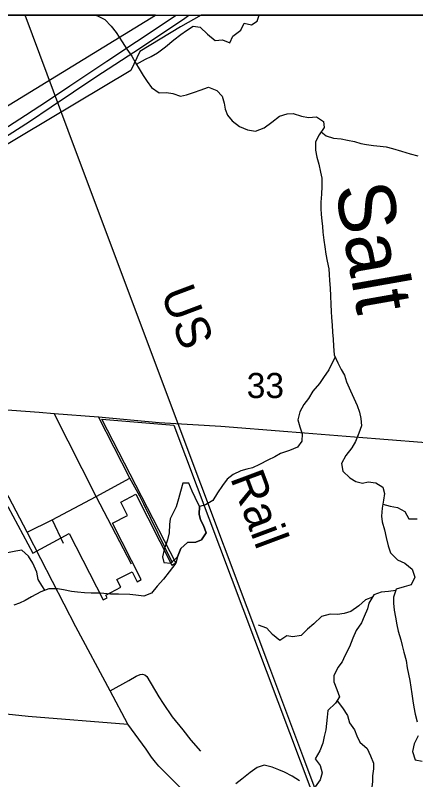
# Model space of a CAD drawing. Extents: x 0 to 34, y 0 to 22.
# Drawn here: x 7.308 to 7.976, y 19.626 to 20.9 of the extents above; entities that cross this region are included whole.
import ezdxf

# ---------------------------------------------------------------- set-up
doc = ezdxf.new("R2010")
doc.units = 0
for name, color, linetype in [('GM_X_City_Street', 7, 'Continuous'), ('GM_X_Corporation', 7, 'Continuous'), ('GM_X_Major_River', 7, 'Continuous'), ('GM_X_Major_River_Text', 7, 'Continuous'), ('GM_X_Minor_Lake', 7, 'Continuous'), ('GM_X_Minor_River', 7, 'Continuous'), ('GM_X_Rail_Line', 7, 'Continuous'), ('GM_X_Rail_Line_Text', 7, 'Continuous'), ('GM_X_Section_Text', 7, 'Continuous'), ('GM_X_State_Route', 7, 'Continuous'), ('GM_X_Township_Road', 7, 'Continuous'), ('SH_Data', 7, 'Continuous')]:
    doc.layers.add(name, color=color, linetype=linetype)

msp = doc.modelspace()

# ---------------------------------------------------------------- linework, layer by layer
at = {"layer": 'GM_X_City_Street'}
for points in [[(7.5486, 20.221), (7.6513, 20.215), (7.7633, 20.2061), (7.8743, 20.1973), (7.9869, 20.1886), (8.0786, 20.1811), (8.1861, 20.1725), (8.2502, 20.1677), (8.257, 20.1674), (8.2667, 20.1684), (8.2777, 20.1709), (8.2899, 20.1745), (8.3049, 20.18), (8.3207, 20.1872), (8.3351, 20.1944), (8.3579, 20.209), (8.4567, 20.2898), (8.4843, 20.3102), (8.5164, 20.3311)], [(7.2032, 20.2492), (7.3486, 20.2383), (7.3732, 20.236), (7.4471, 20.2305), (7.5486, 20.221)]]:
    msp.add_lwpolyline(points, dxfattribs=at)
at = {"layer": 'GM_X_Corporation'}
for points in [[(7.2218, 20.7043), (7.5423, 20.9), (5.1364, 20.9)], [(8.0548, 20.9), (7.6183, 20.9), (7.5838, 20.8809), (7.5164, 20.8398), (7.501, 20.8077), (7.2272, 20.6445)], [(7.2961, 20.0811), (7.3375, 20.0037), (7.3985, 20.0362), (7.4549, 19.9255), (7.4616, 19.929), (7.4595, 19.9333), (7.4846, 19.9466), (7.4781, 19.9593), (7.5032, 19.9726), (7.5118, 19.9557), (7.5185, 19.9593), (7.4706, 20.0533), (7.4956, 20.0664), (7.4844, 20.0884), (7.5095, 20.1018), (7.5696, 19.9836), (7.5763, 19.9872), (7.4527, 20.2266), (7.573, 20.2166), (7.8422, 19.5022)]]:
    msp.add_lwpolyline(points, dxfattribs=at)
at = {"layer": 'GM_X_Major_River'}
for points in [[(7.4415, 20.9), (7.4456, 20.8989), (7.4577, 20.8931), (7.4686, 20.8817), (7.4765, 20.8714), (7.4869, 20.8557), (7.4948, 20.8435), (7.503, 20.8317), (7.509, 20.821), (7.515, 20.8107), (7.5217, 20.7997), (7.5284, 20.7894), (7.5356, 20.7795), (7.5484, 20.7706), (7.5609, 20.7713), (7.5711, 20.7697), (7.5843, 20.765), (7.5942, 20.7672), (7.6075, 20.7717), (7.617, 20.7754), (7.6307, 20.7802), (7.6447, 20.7748), (7.6533, 20.7653), (7.657, 20.7535), (7.6588, 20.7436), (7.6625, 20.7333), (7.67, 20.7238), (7.6824, 20.7146), (7.696, 20.7091), (7.7093, 20.7068), (7.7237, 20.7123), (7.7363, 20.7221), (7.7493, 20.7319), (7.7618, 20.7356), (7.7721, 20.7362), (7.7857, 20.732), (7.7978, 20.7296), (7.8107, 20.7306), (7.8224, 20.7229), (7.8238, 20.7127), (7.8154, 20.701), (7.8092, 20.6889), (7.8094, 20.6752), (7.8116, 20.6635), (7.8146, 20.6521), (7.8175, 20.6384), (7.8197, 20.6285), (7.8199, 20.6148), (7.8191, 20.6019), (7.8182, 20.5887), (7.8181, 20.5777), (7.8188, 20.5678), (7.8198, 20.5575), (7.8209, 20.548), (7.8216, 20.5386), (7.8233, 20.5253), (7.8248, 20.5142), (7.8266, 20.5021), (7.8287, 20.4903), (7.8313, 20.4774), (7.8323, 20.4679)], [(7.8323, 20.4679), (7.8326, 20.458), (7.834, 20.4451), (7.8343, 20.4326), (7.8349, 20.4178), (7.8356, 20.406), (7.8359, 20.3965), (7.8369, 20.3836), (7.8376, 20.3719), (7.8386, 20.3601), (7.8393, 20.3487), (7.8403, 20.3339), (7.8463, 20.3206), (7.8518, 20.3095), (7.8575, 20.3), (7.8612, 20.2893), (7.8675, 20.2741), (7.873, 20.2619), (7.8786, 20.2494), (7.8827, 20.2387), (7.8849, 20.2281), (7.8859, 20.2155), (7.8817, 20.2034), (7.8758, 20.1894), (7.8701, 20.1789), (7.8597, 20.1664), (7.8528, 20.1528), (7.855, 20.1403), (7.8666, 20.1292), (7.8764, 20.123), (7.8878, 20.1199), (7.8973, 20.1225), (7.9098, 20.1209), (7.9218, 20.1136), (7.9244, 20.1029), (7.9228, 20.0919), (7.9204, 20.0787), (7.9191, 20.065), (7.9206, 20.0555), (7.9243, 20.0422), (7.9272, 20.0293), (7.9305, 20.0156), (7.9345, 20.0038), (7.9458, 19.9923), (7.9583, 19.9865), (7.9707, 19.9766), (7.9748, 19.9637), (7.969, 19.9508), (7.9572, 19.9475), (7.9439, 19.9434), (7.9396, 19.9302), (7.9395, 19.9203), (7.9406, 19.9085), (7.9427, 19.8967), (7.9449, 19.8842), (7.9471, 19.8732), (7.9515, 19.8591), (7.9541, 19.8496), (7.9566, 19.8386), (7.9603, 19.8245), (7.9621, 19.8124), (7.9665, 19.7911), (7.9683, 19.7801), (7.9701, 19.7687), (7.9715, 19.7573), (7.9733, 19.7466), (7.9755, 19.7349), (7.9788, 19.7223)], [(7.9805, 19.6988), (7.9739, 19.6859), (7.9708, 19.6727), (7.9756, 19.659), (7.987, 19.6566)]]:
    msp.add_lwpolyline(points, dxfattribs=at)
at = {"layer": 'GM_X_Minor_Lake'}
for points in [[(7.6159, 20.0812), (7.6088, 20.0964), (7.6035, 20.107), (7.5979, 20.12), (7.5877, 20.12), (7.5838, 20.1063), (7.5808, 20.0938), (7.5766, 20.0806), (7.572, 20.0707), (7.567, 20.0609), (7.5659, 20.051), (7.5651, 20.0374), (7.5624, 20.0256), (7.557, 20.0097), (7.5539, 19.9976), (7.5562, 19.9877), (7.5679, 19.9866), (7.5793, 19.9975)], [(7.5793, 19.9975), (7.5847, 20.0112), (7.596, 20.0214), (7.6097, 20.0217), (7.6191, 20.0258), (7.6267, 20.0376), (7.6223, 20.0497), (7.6174, 20.0592), (7.6151, 20.0687), (7.6159, 20.0812)]]:
    msp.add_lwpolyline(points, dxfattribs=at)
at = {"layer": 'GM_X_Minor_River'}
for points in [[(7.5106, 20.8183), (7.5258, 20.8267), (7.5352, 20.8312), (7.5455, 20.8376), (7.5588, 20.8474), (7.5728, 20.8591), (7.5846, 20.8678), (7.594, 20.8746), (7.6054, 20.8818), (7.6168, 20.8802), (7.6292, 20.8688), (7.642, 20.8578), (7.6542, 20.8589), (7.6666, 20.8539), (7.6712, 20.8652), (7.6845, 20.8754), (7.6902, 20.8868), (7.7023, 20.8841), (7.7118, 20.8901), (7.7151, 20.9)], [(7.8187, 20.7056), (7.8273, 20.699), (7.8394, 20.6952), (7.8523, 20.694), (7.8629, 20.6921), (7.8742, 20.6894), (7.8848, 20.6863), (7.8946, 20.6844), (7.906, 20.6828), (7.9173, 20.6816), (7.9272, 20.6805), (7.9378, 20.6778), (7.9525, 20.6736), (7.9669, 20.669), (7.9801, 20.6659)], [(7.842, 20.3301), (7.8359, 20.3186), (7.8313, 20.3088), (7.8225, 20.2963), (7.8161, 20.2865), (7.8047, 20.2732), (7.7974, 20.2615), (7.7898, 20.2513), (7.783, 20.2388), (7.7799, 20.2259), (7.7829, 20.2141), (7.787, 20.2024), (7.7862, 20.1899), (7.779, 20.18), (7.7661, 20.1744), (7.751, 20.1695), (7.7415, 20.1642), (7.7297, 20.1586), (7.7161, 20.1514), (7.7043, 20.1458), (7.6945, 20.1435), (7.6846, 20.1405), (7.6717, 20.1345), (7.6619, 20.1266), (7.6543, 20.1163), (7.6459, 20.1039), (7.6379, 20.091), (7.6258, 20.0842), (7.6159, 20.0812), (7.6151, 20.0687), (7.6174, 20.0592), (7.6223, 20.0497), (7.6267, 20.0376), (7.6191, 20.0258), (7.6097, 20.0217), (7.596, 20.0214), (7.5847, 20.0112), (7.5793, 19.9975), (7.5762, 19.9865), (7.5652, 19.9725), (7.5557, 19.9601), (7.5451, 19.9483), (7.5356, 19.9366), (7.5227, 19.9317), (7.5094, 19.9333), (7.4996, 19.9345), (7.4807, 19.9349), (7.4674, 19.9353), (7.4508, 19.9369), (7.4353, 19.937), (7.4239, 19.9374), (7.4122, 19.9385), (7.402, 19.9397), (7.3891, 19.9424), (7.3789, 19.944), (7.3642, 19.944), (7.3513, 19.9388), (7.3357, 19.9308), (7.3247, 19.9248), (7.3153, 19.9203), (7.3058, 19.9165)], [(7.9215, 20.085), (7.9338, 20.0816), (7.9463, 20.0797), (7.958, 20.0728), (7.9652, 20.0607), (7.9788, 20.0606)], [(7.3579, 19.9415), (7.3528, 19.9497), (7.3464, 19.9593), (7.3442, 19.9718), (7.3378, 19.987), (7.3307, 19.9987), (7.3193, 20.0083), (7.3095, 20.0068), (7.2955, 20.0042), (7.2826, 20.0038), (7.2698, 20.0065), (7.2525, 20.0151)], [(7.9432, 19.9413), (7.9311, 19.9398), (7.919, 19.9384), (7.9068, 19.9342), (7.8981, 19.9202), (7.8962, 19.9107), (7.8904, 19.8979), (7.8862, 19.8873), (7.8771, 19.8744), (7.8714, 19.8615), (7.8657, 19.8471), (7.8584, 19.8324), (7.8538, 19.8225), (7.8466, 19.8127), (7.8398, 19.7991), (7.8401, 19.7892), (7.8446, 19.7763), (7.8495, 19.7638), (7.8426, 19.7532), (7.8301, 19.7411), (7.8289, 19.7301), (7.8278, 19.7195), (7.8266, 19.7092), (7.8235, 19.6979), (7.8216, 19.6869), (7.8166, 19.674), (7.8086, 19.6604), (7.8173, 19.6497), (7.8203, 19.6372), (7.8172, 19.6258), (7.8085, 19.6137)], [(7.9044, 19.9303), (7.8924, 19.9255), (7.8818, 19.9157), (7.8681, 19.9063), (7.8571, 19.9029), (7.8462, 19.9014), (7.8337, 19.9015), (7.8193, 19.8981), (7.8064, 19.8856), (7.7957, 19.877), (7.7855, 19.8664), (7.7715, 19.8638), (7.7616, 19.8657), (7.7495, 19.8581), (7.7378, 19.8677), (7.728, 19.8787), (7.7144, 19.8837)], [(7.8453, 19.7572), (7.8543, 19.7455), (7.8626, 19.733), (7.866, 19.7205), (7.8743, 19.7091), (7.878, 19.6992), (7.8833, 19.6886), (7.8954, 19.6779), (7.901, 19.6657), (7.9062, 19.6532), (7.9058, 19.6437), (7.9043, 19.6324), (7.9046, 19.6225), (7.9027, 19.6096), (7.9011, 19.5975), (7.9022, 19.5846), (7.8999, 19.5751), (7.8905, 19.571)], [(7.7824, 19.6241), (7.7703, 19.6317), (7.7578, 19.6385), (7.748, 19.6424), (7.7371, 19.6466), (7.7234, 19.65), (7.7121, 19.6463), (7.7003, 19.6376), (7.6863, 19.627), (7.6764, 19.6187)]]:
    msp.add_lwpolyline(points, dxfattribs=at)
at = {"layer": 'GM_X_Rail_Line'}
for points in [[(7.7899, 19.661), (7.7331, 19.8124), (7.5803, 20.2192), (7.4092, 20.6751), (7.3247, 20.9)], [(8.1892, 18.5986), (8.0513, 18.9649), (7.8912, 19.3911), (7.7899, 19.661)]]:
    msp.add_lwpolyline(points, dxfattribs=at)
at = {"layer": 'GM_X_State_Route'}
for points in [[(7.2785, 20.6898), (7.2982, 20.7015), (7.3321, 20.723), (7.3682, 20.7474), (7.4055, 20.7724), (7.443, 20.7974), (7.5175, 20.8456), (7.5911, 20.8953), (7.5981, 20.9)], [(7.2878, 20.7088), (7.3254, 20.7336), (7.3623, 20.7573), (7.3994, 20.7823), (7.4611, 20.8238), (7.5108, 20.8561), (7.5767, 20.9)], [(7.351, 19.9942), (7.3282, 20.0384), (7.2977, 20.0968), (7.2702, 20.1418), (7.2389, 20.192)], [(7.4965, 19.7186), (7.4668, 19.774), (7.4096, 19.8809), (7.351, 19.9942)], [(7.5424, 19.6552), (7.5357, 19.6632), (7.5268, 19.6769), (7.5148, 19.6935), (7.4965, 19.7186)], [(7.6259, 19.587), (7.6153, 19.5921), (7.5902, 19.6059), (7.5479, 19.6486), (7.5424, 19.6552)]]:
    msp.add_lwpolyline(points, dxfattribs=at)
at = {"layer": 'GM_X_Township_Road'}
for p, q in [((7.571, 19.9872), (7.5228, 20.085)), ((7.3701, 20.0591), (7.3882, 20.0199))]:
    msp.add_line(p, q, dxfattribs=at)
for points in [[(7.5026, 19.9852), (7.4436, 20.0977), (7.3732, 20.236)], [(7.5228, 20.085), (7.5161, 20.0987), (7.4994, 20.1287), (7.4471, 20.2305)], [(7.3282, 20.0384), (7.3701, 20.0591), (7.4436, 20.0977), (7.4994, 20.1287)], [(7.4668, 19.774), (7.4978, 19.7912), (7.5102, 19.7982), (7.5166, 19.8012), (7.5207, 19.8015), (7.5246, 19.8004), (7.5277, 19.7978), (7.5479, 19.7638), (7.5552, 19.7528)], [(6.5209, 19.7864), (6.6067, 19.7786), (6.7488, 19.7702), (6.9834, 19.759), (7.0732, 19.7546), (7.2824, 19.7367), (7.33, 19.7319), (7.4965, 19.7186)], [(7.5552, 19.7528), (7.5699, 19.7309), (7.5878, 19.7087), (7.6012, 19.6919), (7.6175, 19.6732)]]:
    msp.add_lwpolyline(points, dxfattribs=at)
at = {"layer": 'SH_Data'}
msp.add_line((2.1, 20.9), (8.9, 20.9), dxfattribs=at)

# ---------------------------------------------------------------- texts
at = {"layer": 'GM_X_Major_River_Text'}
msp.add_text('Salt', height=0.09471, rotation=279.9997, dxfattribs=at).set_placement((7.8417, 20.6136))
at = {"layer": 'GM_X_Rail_Line_Text'}
for s, rotation, p in [('US', 290.6025, (7.5506, 20.4373)), ('Rail', 290.4835, (7.6665, 20.1289))]:
    msp.add_text(s, height=0.05663, rotation=rotation, dxfattribs=at).set_placement(p)
at = {"layer": 'GM_X_Section_Text'}
msp.add_text('33', height=0.04186, rotation=0, dxfattribs=at).set_placement((7.6945, 20.262))

doc.saveas('drawing.dxf')
